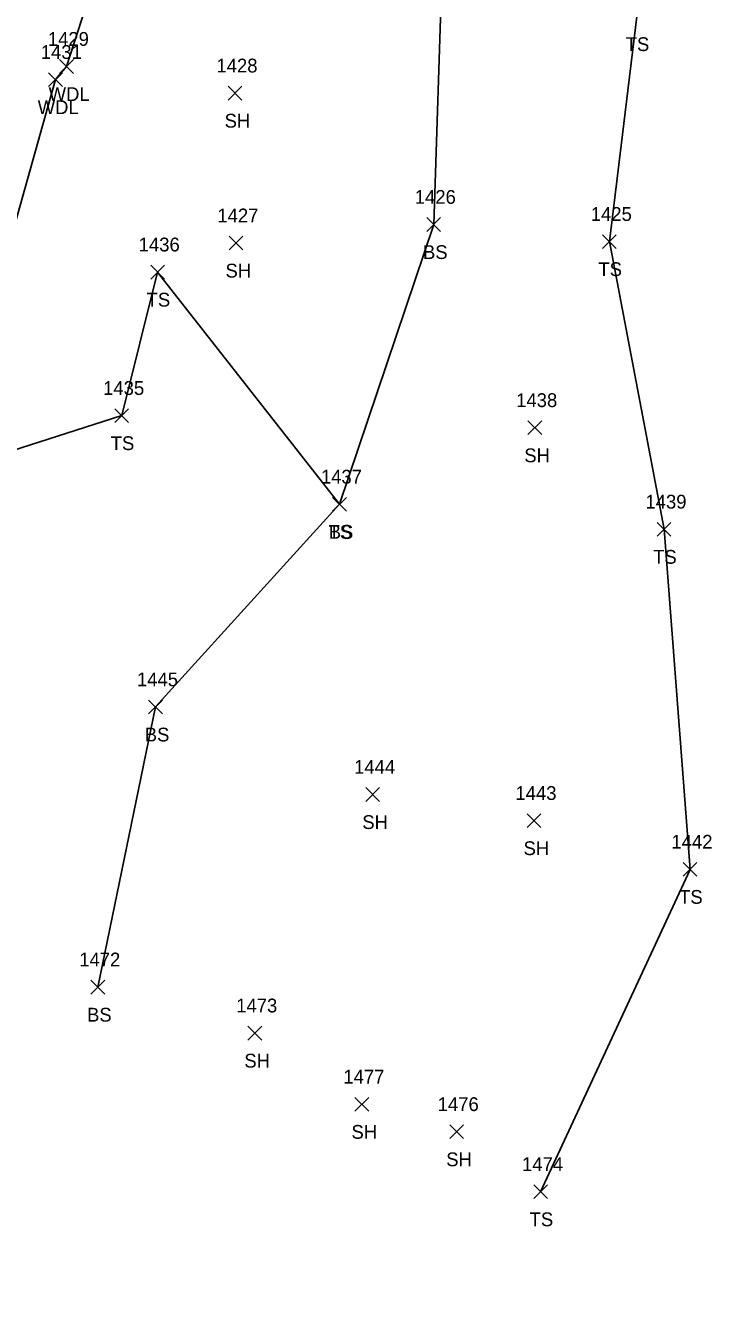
# Model space of a CAD drawing. Extents: x 1551995 to 1555700, y 777276 to 783130.
# Drawn here: x 1554870.3 to 1554969.7, y 777462.7 to 777646.9 of the extents above; entities that cross this region are included whole.
import ezdxf

# ---------------------------------------------------------------- set-up
doc = ezdxf.new("R2010")
doc.units = 0
for name, color, linetype in [('L_A', 7, 'Continuous'), ('L_I', 7, 'Continuous'), ('L_TIC', 7, 'Continuous'), ('LAWA', 7, 'Continuous'), ('LELB', 7, 'Continuous')]:
    doc.layers.add(name, color=color, linetype=linetype)

msp = doc.modelspace()

# ---------------------------------------------------------------- linework, layer by layer
at = {"layer": 'L_TIC'}
for points in [[(1554875.24, 777639.92), (1554877.24, 777641.92)], [(1554877.24, 777639.92), (1554875.24, 777641.92)], [(1554873.65, 777638.02), (1554875.65, 777640.02)], [(1554875.65, 777638.02), (1554873.65, 777640.02)], [(1554899.66, 777636.06), (1554901.66, 777638.06)], [(1554901.66, 777636.06), (1554899.66, 777638.06)], [(1554928.45, 777617.01), (1554930.45, 777619.01)], [(1554930.45, 777617.01), (1554928.45, 777619.01)], [(1554899.79, 777614.32), (1554901.79, 777616.32)], [(1554901.79, 777614.32), (1554899.79, 777616.32)], [(1554953.89, 777614.53), (1554955.89, 777616.53)], [(1554955.89, 777614.53), (1554953.89, 777616.53)], [(1554888.44, 777610.11), (1554890.44, 777612.11)], [(1554890.44, 777610.11), (1554888.44, 777612.11)], [(1554883.24, 777589.3), (1554885.24, 777591.3)], [(1554885.24, 777589.3), (1554883.24, 777591.3)], [(1554943.09, 777587.54), (1554945.09, 777589.54)], [(1554945.09, 777587.54), (1554943.09, 777589.54)], [(1554914.79, 777576.44), (1554916.79, 777578.44)], [(1554916.79, 777576.44), (1554914.79, 777578.44)], [(1554914.79, 777576.44), (1554916.79, 777578.44)], [(1554916.79, 777576.44), (1554914.79, 777578.44)], [(1554961.82, 777572.82), (1554963.82, 777574.82)], [(1554963.82, 777572.82), (1554961.82, 777574.82)], [(1554888.14, 777547.05), (1554890.14, 777549.05)], [(1554890.14, 777547.05), (1554888.14, 777549.05)], [(1554919.61, 777534.36), (1554921.61, 777536.36)], [(1554921.61, 777534.36), (1554919.61, 777536.36)], [(1554942.97, 777530.57), (1554944.97, 777532.57)], [(1554944.97, 777530.57), (1554942.97, 777532.57)], [(1554965.58, 777523.51), (1554967.58, 777525.51)], [(1554967.58, 777523.51), (1554965.58, 777525.51)], [(1554879.78, 777506.43), (1554881.78, 777508.43)], [(1554881.78, 777506.43), (1554879.78, 777508.43)], [(1554902.52, 777499.76), (1554904.52, 777501.76)], [(1554904.52, 777499.76), (1554902.52, 777501.76)], [(1554918.04, 777489.44), (1554920.04, 777491.44)], [(1554920.04, 777489.44), (1554918.04, 777491.44)], [(1554931.77, 777485.46), (1554933.77, 777487.46)], [(1554933.77, 777485.46), (1554931.77, 777487.46)], [(1554943.93, 777476.76), (1554945.93, 777478.76)], [(1554945.93, 777476.76), (1554943.93, 777478.76)]]:
    msp.add_lwpolyline(points, dxfattribs=at)
at = {"layer": 'LAWA'}
msp.add_lwpolyline([(1554924.17, 777845.95), (1554911.99, 777797.39), (1554901.73, 777752.36), (1554891.43, 777715.92), (1554886.53, 777681.63), (1554885.54, 777676.35), (1554886.43, 777672.72), (1554885.1, 777668.28), (1554876.24, 777640.92), (1554874.65, 777639.02), (1554865.05, 777604.93), (1554832.26, 777556.58), (1554828.6, 777545), (1554825.77, 777534.55), (1554825.26, 777531.03), (1554824.11, 777527.47), (1554817.13, 777514.36), (1554810.78, 777500.84), (1554797.7, 777469.38), (1554813.54, 777462.7)], dxfattribs=at)
at = {"layer": 'LELB'}
for points in [[(1554930.69, 777655.48), (1554929.45, 777618.01), (1554915.79, 777577.44), (1554889.14, 777548.05), (1554880.78, 777507.43)], [(1554958.85, 777648.16), (1554954.89, 777615.53), (1554962.82, 777573.82), (1554966.58, 777524.51), (1554944.93, 777477.76)], [(1554861.66, 777583.06), (1554884.24, 777590.3), (1554889.44, 777611.11), (1554915.79, 777577.44)]]:
    msp.add_lwpolyline(points, dxfattribs=at)

# ---------------------------------------------------------------- texts
at = {"layer": 'L_A'}
for s, p in [('TS', (1554957.26, 777643.16)), ('TS', (1554957.26, 777643.16)), ('WDL', (1554873.66, 777635.92)), ('WDL', (1554872.07, 777634.02)), ('SH', (1554899.15, 777632.06)), ('BS', (1554927.89, 777613.01)), ('SH', (1554899.28, 777610.32)), ('TS', (1554953.3, 777610.53)), ('TS', (1554887.85, 777606.11)), ('TS', (1554882.65, 777585.3)), ('SH', (1554942.57, 777583.54)), ('TS', (1554914.2, 777572.44)), ('BS', (1554914.23, 777572.44)), ('TS', (1554961.23, 777568.82)), ('BS', (1554887.58, 777543.05)), ('SH', (1554919.1, 777530.36)), ('SH', (1554942.46, 777526.57)), ('TS', (1554964.99, 777519.51)), ('BS', (1554879.22, 777502.43)), ('SH', (1554902.01, 777495.76)), ('SH', (1554917.53, 777485.44)), ('SH', (1554931.26, 777481.46)), ('TS', (1554943.34, 777472.76))]:
    msp.add_text(s, height=2, dxfattribs=at).set_placement(p)
at = {"layer": 'L_I'}
for s, p in [('1429', (1554873.54, 777643.92)), ('1431', (1554872.52, 777642.02)), ('1428', (1554897.97, 777640.06)), ('1426', (1554926.7, 777621.01)), ('1425', (1554952.2, 777618.53)), ('1427', (1554898.1, 777618.32)), ('1436', (1554886.7, 777614.11)), ('1435', (1554881.55, 777593.3)), ('1438', (1554941.39, 777591.54)), ('1437', (1554913.1, 777580.44)), ('1437', (1554913.1, 777580.44)), ('1439', (1554960.12, 777576.82)), ('1445', (1554886.45, 777551.05)), ('1444', (1554917.91, 777538.36)), ('1443', (1554941.28, 777534.57)), ('1442', (1554963.88, 777527.51)), ('1472', (1554878.09, 777510.43)), ('1473', (1554900.83, 777503.76)), ('1477', (1554916.35, 777493.44)), ('1476', (1554930.02, 777489.46)), ('1474', (1554942.24, 777480.76))]:
    msp.add_text(s, height=2, dxfattribs=at).set_placement(p)

doc.saveas('drawing.dxf')
